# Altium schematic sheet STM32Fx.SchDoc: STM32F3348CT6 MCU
size A4; CompanyName: STM; DocumentNumber: MB1142; Revision: B-01; SheetNumber: 3; SheetTotal: 5; PageSetup: Record=PageOptions|CenterHorizontal=True|CenterVertical=True|PrintScale=1.00|XCorrection=1.00|YCorrection=1.00|PrintKind=0|BorderSize=5000000|LeftOffset=0|BottomOffset=0|Orientation=2|PaperLength=1000|PaperWidth=1000|Scale=100|PaperSource=7|PrintQuality=-4|MediaType=1|DitherType=10|PaperKind=A4|PrintScaleMode=1; Project: STM32F3348-DISCO
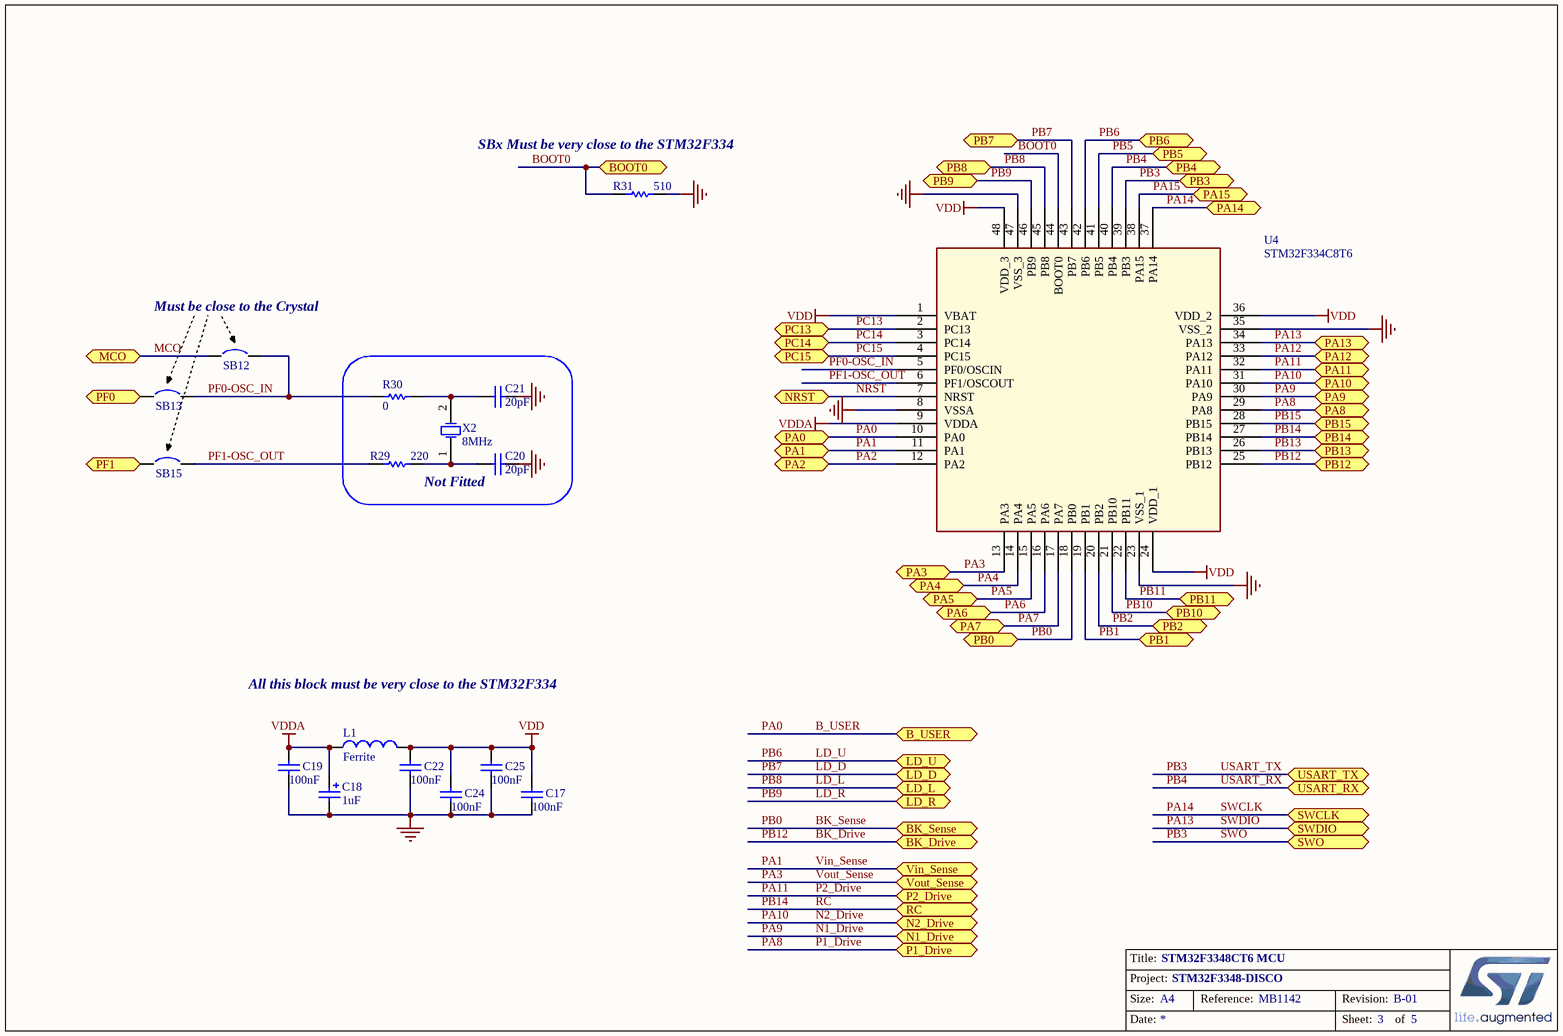
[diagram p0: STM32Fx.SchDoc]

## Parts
C17  100nF  [0402C]
C18  1uF  [TAN-A]
C19  100nF  [0402C]
C20  20pF  [0402C]
C21  20pF  [0402C]
C22  100nF  [0402C]
C24  100nF  [0402C]
C25  100nF  [0402C]
L1  Ferrite  [0603L]
R29  220  [0402R]
R30  0  [0402R]
R31  510  [0402R]
SB12  Circuit Breaker  [JP2_SMD]  (value not drawn)
SB13  Circuit Breaker  [JP2_SMD]  (value not drawn)
SB15  Circuit Breaker  [JP2_SMD]  (value not drawn)
U4  STM32F334C8T6  [QFP48 7X7]
X2  8MHz  [XTAL1]

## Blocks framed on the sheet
Not Fitted: C20 C21 R29 R30 X2

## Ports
B_USER, BK_Drive, BK_Sense, BOOT0, LD_D, LD_L, LD_R, LD_U, MCO, N1_Drive, N2_Drive, NRST, P1_Drive, P2_Drive, PA0, PA1, PA2, PA3, PA4, PA5, PA6, PA7, PA8, PA9, PA10, PA11, PA12, PA13, PA14, PA15, PB0, PB1, PB2, PB3, PB4, PB5, PB6, PB7, PB8, PB9, PB10, PB11, PB12, PB13, PB14, PB15, PC13, PC14, PC15, PF0, PF1, RC, SWCLK, SWDIO, SWO, USART_RX, USART_TX, Vin_Sense, Vout_Sense

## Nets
GND: C17.1 C18.2 C19.1 C20.1 C21.1 C22.1 C24.1 C25.2 R31.2 U4.8(VSSA) U4.23(VSS_1) U4.35(VSS_2) U4.47(VSS_3)
VDD: C17.2 C22.2 C24.2 C25.1 L1.2 U4.1(VBAT) U4.24(VDD_1) U4.36(VDD_2) U4.48(VDD_3)
VDDA: C18.1 C19.2 L1.1 U4.9(VDDA)
B_USER: U4.10(PA0) ; port PA0, port B_USER  [also labelled PA0]
BK_Drive: U4.25(PB12) ; port PB12, port BK_Drive  [also labelled PB12]
BK_Sense: U4.18(PB0) ; port PB0, port BK_Sense  [also labelled PB0]
BOOT0: R31.1 U4.44(BOOT0) ; port BOOT0
LD_D: U4.43(PB7) ; port PB7, port LD_D  [also labelled PB7]
LD_L: U4.45(PB8) ; port PB8, port LD_L  [also labelled PB8]
LD_R: U4.46(PB9) ; port PB9, port LD_R  [also labelled PB9]
LD_U: U4.42(PB6) ; port PB6, port LD_U  [also labelled PB6]
MCO: SB12.1 ; port MCO
N1_Drive: U4.30(PA9) ; port PA9, port N1_Drive  [also labelled PA9]
N2_Drive: U4.31(PA10) ; port PA10, port N2_Drive  [also labelled PA10]
NRST: U4.7(NRST) ; port NRST
P1_Drive: U4.29(PA8) ; port PA8, port P1_Drive  [also labelled PA8]
P2_Drive: U4.32(PA11) ; port PA11, port P2_Drive  [also labelled PA11]
PA1: U4.11(PA1) ; port PA1, port Vin_Sense  [also labelled Vin_Sense]
PA2: U4.12(PA2) ; port PA2
PA3: U4.13(PA3) ; port PA3, port Vout_Sense  [also labelled Vout_Sense]
PA4: U4.14(PA4) ; port PA4
PA5: U4.15(PA5) ; port PA5
PA6: U4.16(PA6) ; port PA6
PA7: U4.17(PA7) ; port PA7
PA12: U4.33(PA12) ; port PA12
PA13: U4.34(PA13) ; port PA13, port SWDIO  [also labelled SWDIO]
PA14: U4.37(PA14) ; port PA14, port SWCLK  [also labelled SWCLK]
PA15: U4.38(PA15) ; port PA15
PB1: U4.19(PB1) ; port PB1
PB2: U4.20(PB2) ; port PB2
PB3: U4.39(PB3) ; port PB3, port USART_TX, port SWO  [also labelled SWO, USART_TX]
PB4: U4.40(PB4) ; port PB4, port USART_RX  [also labelled USART_RX]
PB5: U4.41(PB5) ; port PB5
PB10: U4.21(PB10) ; port PB10
PB11: U4.22(PB11) ; port PB11
PB13: U4.26(PB13) ; port PB13
PB14: U4.27(PB14) ; port PB14, port RC  [also labelled RC]
PB15: U4.28(PB15) ; port PB15
PC13: U4.2(PC13) ; port PC13
PC14: U4.3(PC14) ; port PC14
PC15: U4.4(PC15) ; port PC15
PF0: SB13.1 ; port PF0
PF0-OSC_IN: R30.1 SB12.2 SB13.2 U4.5(PF0/OSCIN)
PF1: SB15.1 ; port PF1
PF1-OSC_OUT: R29.2 SB15.2 U4.6(PF1/OSCOUT)
NetC20_2: C20.2 R29.1 X2.1(OSC1)
NetC21_2: C21.2 R30.2 X2.2(OSC2)

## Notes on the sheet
- (near R31) SBx Must be very close to the STM32F334
- (near SB12) Must be close to the Crystal
- All this block must be very close to the STM32F334

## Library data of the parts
C17 C19 C22 C24 C25 = Cap_100nF_X7R_10%_0402: Capacitor,100nF,16V,X7R,10%,0402,YAGEO; Manuf_Part_1: CC0402KRX7R7BB104
C18 = Cap_1uF_POL_10%_TANA: Polarized Capacitor,1uF,16V,10%,typeA,AVX; Manuf_Part_1: TAJA105K016R
C20 C21 = Cap_20pF_NPO_5%_0402: Capacitor,20pF,50V,NPO,5%,0402,YAGEO; Order: CC0402JRNPO9BN200; Fitted: NO
L1 = BEAD_600R_350MA_0603: Bead,600R,350mA,0603,FCM1608KF-601T03,Tai-tech; Manuf_2: TDK; Manuf_Part_2: MPZ1608S300A; Value: 100uH; Comment_1: bead,30R,5A,0603,MPZ1608S300A,TDK
R29 = Res1: Resistor; Fitted: NO
R30 = Res_0_0402: Resistor,0,0402; Fitted: NO
R31 = Resistor_ST: Resistor 0402 / 0603 / 0805; Description: Resistor 0402 or 0603 or 0805; Value: 10K
SB12 = Circuit Breaker: Solder: YES
SB13 SB15 = Circuit Breaker: Solder: NO
U4 = STM32F334C8T6: Medium-density performance line ARM-based 32-bit MCU with 64KB Flash and High Resolution Timer; Manuf_1: STM; Ref St: xxxxxxxxx; Provided: ST; ECCN_US/EU: 3A991A2/NEC
X2 = XTAL: Crystal Oscillator,8Mhz,20PF,20PPM,-10-70 degree,DIP,HC-49S; Manuf_Part_1: 9SL8000020AFXHF0; ECCN_US/EU: EAR99/NEC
